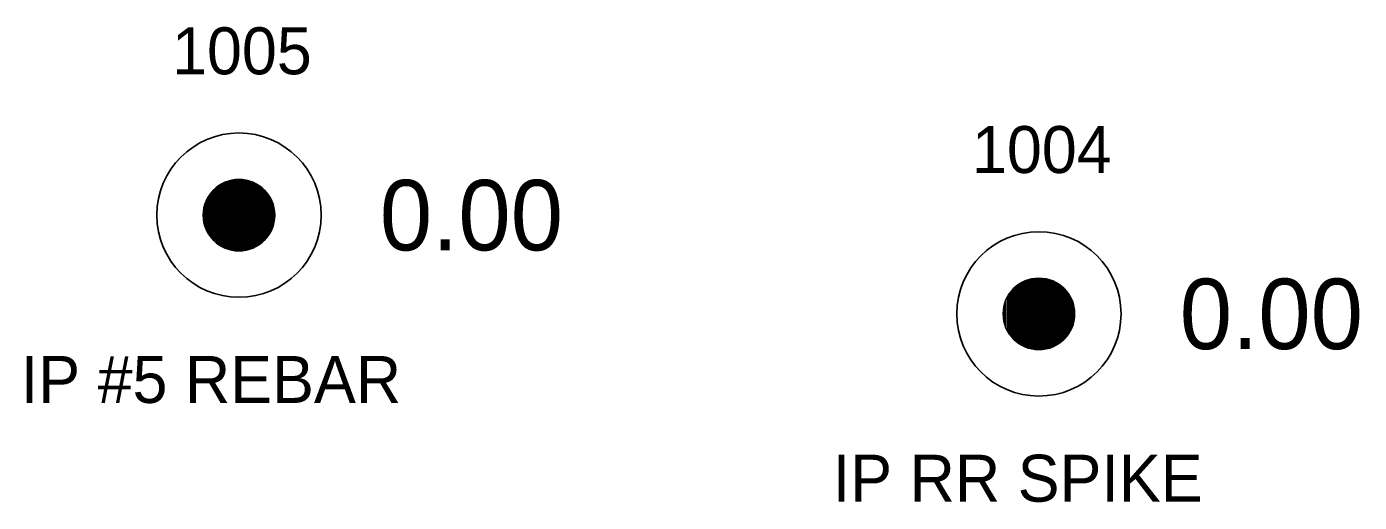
# Model space of a CAD drawing. Extents: x 1740701 to 1743138, y 748181 to 751839.
# Drawn here: x 1740736.52 to 1740764.9, y 749291.94 to 749302.07 of the extents above; entities that cross this region are included whole.
import ezdxf

# ---------------------------------------------------------------- set-up
doc = ezdxf.new("R2010")
doc.units = 0
for name, color, linetype in [('RD_EX_DV_Prop_txCode', 7, 'Continuous'), ('RD_EX_DV_PropPin', 7, 'Continuous'), ('RD_EX_TX_DV_Prop_ELEV', 7, 'Continuous'), ('RD_SMD_Locator', 7, 'Continuous')]:
    doc.layers.add(name, color=color, linetype=linetype)

msp = doc.modelspace()

# ---------------------------------------------------------------- linework, layer by layer
at = {"layer": 'RD_EX_DV_PropPin'}
for p, q in [((1740740.513, 749297.502), (1740740.513, 749298.604)), ((1740740.548, 749297.471), (1740740.548, 749298.635)), ((1740740.583, 749297.443), (1740740.583, 749298.663)), ((1740740.618, 749297.418), (1740740.618, 749298.687)), ((1740740.653, 749297.396), (1740740.653, 749298.709)), ((1740740.688, 749297.377), (1740740.688, 749298.728)), ((1740740.723, 749297.36), (1740740.723, 749298.746)), ((1740740.758, 749297.345), (1740740.758, 749298.76)), ((1740740.793, 749297.332), (1740740.793, 749298.773)), ((1740740.828, 749297.321), (1740740.828, 749298.784)), ((1740740.863, 749297.312), (1740740.863, 749298.793)), ((1740740.898, 749297.305), (1740740.898, 749298.801)), ((1740740.933, 749297.299), (1740740.933, 749298.807)), ((1740740.968, 749297.295), (1740740.968, 749298.811)), ((1740741.003, 749297.293), (1740741.003, 749298.813)), ((1740741.038, 749297.292), (1740741.038, 749298.814)), ((1740741.073, 749297.293), (1740741.073, 749298.813)), ((1740741.108, 749297.295), (1740741.108, 749298.811)), ((1740741.143, 749297.299), (1740741.143, 749298.807)), ((1740741.178, 749297.305), (1740741.178, 749298.801)), ((1740741.213, 749297.312), (1740741.213, 749298.793)), ((1740741.248, 749297.321), (1740741.248, 749298.784)), ((1740741.283, 749297.332), (1740741.283, 749298.773)), ((1740741.318, 749297.345), (1740741.318, 749298.76)), ((1740741.353, 749297.36), (1740741.353, 749298.746)), ((1740741.388, 749297.377), (1740741.388, 749298.728)), ((1740741.423, 749297.396), (1740741.423, 749298.709)), ((1740741.458, 749297.418), (1740741.458, 749298.687)), ((1740741.493, 749297.443), (1740741.493, 749298.663)), ((1740741.528, 749297.471), (1740741.528, 749298.635)), ((1740741.563, 749297.502), (1740741.563, 749298.604)), ((1740740.338, 749297.755), (1740740.338, 749298.351)), ((1740740.373, 749297.683), (1740740.373, 749298.422)), ((1740740.408, 749297.626), (1740740.408, 749298.479)), ((1740740.443, 749297.579), (1740740.443, 749298.527)), ((1740740.478, 749297.538), (1740740.478, 749298.568)), ((1740741.598, 749297.538), (1740741.598, 749298.568)), ((1740741.633, 749297.579), (1740741.633, 749298.527)), ((1740741.668, 749297.626), (1740741.668, 749298.479)), ((1740741.703, 749297.683), (1740741.703, 749298.422)), ((1740741.738, 749297.755), (1740741.738, 749298.351)), ((1740740.303, 749297.857), (1740740.303, 749298.249)), ((1740741.773, 749297.857), (1740741.773, 749298.249)), ((1740757.692, 749295.294), (1740757.692, 749296.606)), ((1740757.727, 749295.274), (1740757.727, 749296.626)), ((1740757.762, 749295.257), (1740757.762, 749296.643)), ((1740757.797, 749295.242), (1740757.797, 749296.658)), ((1740757.832, 749295.23), (1740757.832, 749296.67)), ((1740757.867, 749295.219), (1740757.867, 749296.681)), ((1740757.902, 749295.209), (1740757.902, 749296.691)), ((1740757.937, 749295.202), (1740757.937, 749296.698)), ((1740757.972, 749295.196), (1740757.972, 749296.704)), ((1740758.007, 749295.192), (1740758.007, 749296.708)), ((1740758.042, 749295.19), (1740758.042, 749296.71)), ((1740758.077, 749295.189), (1740758.077, 749296.711)), ((1740758.112, 749295.19), (1740758.112, 749296.71)), ((1740758.147, 749295.192), (1740758.147, 749296.708)), ((1740758.182, 749295.196), (1740758.182, 749296.704)), ((1740758.217, 749295.202), (1740758.217, 749296.698)), ((1740758.252, 749295.209), (1740758.252, 749296.691)), ((1740758.287, 749295.219), (1740758.287, 749296.681)), ((1740758.322, 749295.23), (1740758.322, 749296.67)), ((1740758.357, 749295.242), (1740758.357, 749296.658)), ((1740758.392, 749295.257), (1740758.392, 749296.643)), ((1740758.427, 749295.274), (1740758.427, 749296.626)), ((1740758.462, 749295.294), (1740758.462, 749296.606)), ((1740757.412, 749295.58), (1740757.412, 749296.32)), ((1740757.447, 749295.523), (1740757.447, 749296.377)), ((1740757.482, 749295.476), (1740757.482, 749296.424)), ((1740757.517, 749295.435), (1740757.517, 749296.465)), ((1740757.552, 749295.399), (1740757.552, 749296.501)), ((1740757.587, 749295.368), (1740757.587, 749296.532)), ((1740757.622, 749295.34), (1740757.622, 749296.56)), ((1740757.657, 749295.315), (1740757.657, 749296.585)), ((1740758.497, 749295.315), (1740758.497, 749296.585)), ((1740758.532, 749295.34), (1740758.532, 749296.56)), ((1740758.567, 749295.368), (1740758.567, 749296.532)), ((1740758.602, 749295.399), (1740758.602, 749296.501)), ((1740758.637, 749295.435), (1740758.637, 749296.465)), ((1740758.672, 749295.476), (1740758.672, 749296.424)), ((1740758.707, 749295.523), (1740758.707, 749296.377)), ((1740758.742, 749295.58), (1740758.742, 749296.32)), ((1740757.341, 749295.754), (1740757.341, 749296.146)), ((1740757.376, 749295.652), (1740757.376, 749296.248)), ((1740758.777, 749295.652), (1740758.777, 749296.248)), ((1740758.812, 749295.754), (1740758.812, 749296.146))]:
    msp.add_line(p, q, dxfattribs=at)
for centre, radius in [((1740741.038, 749298.053), 1.75), ((1740741.038, 749298.053), 0.761), ((1740758.077, 749295.95), 1.75), ((1740758.077, 749295.95), 0.761)]:
    msp.add_circle(centre, radius, dxfattribs=at)
at = {"layer": 'RD_SMD_Locator'}
for centre in [(1740741.038, 749298.053), (1740758.077, 749295.95)]:
    msp.add_circle(centre, 0.15, dxfattribs=at)

# ---------------------------------------------------------------- texts
at = {"layer": 'RD_EX_DV_Prop_txCode'}
for s, p in [('1005', (1740739.613, 749301.053)), ('1004', (1740756.652, 749298.95)), ('IP #5 REBAR', (1740736.392, 749294.053)), ('IP RR SPIKE', (1740753.687, 749291.95))]:
    msp.add_text(s, height=1, dxfattribs=at).set_placement(p)
at = {"layer": 'RD_EX_TX_DV_Prop_ELEV'}
for p in [(1740744.038, 749297.303), (1740761.077, 749295.2)]:
    msp.add_text('0.00', height=1.5, dxfattribs=at).set_placement(p)

doc.saveas('drawing.dxf')
